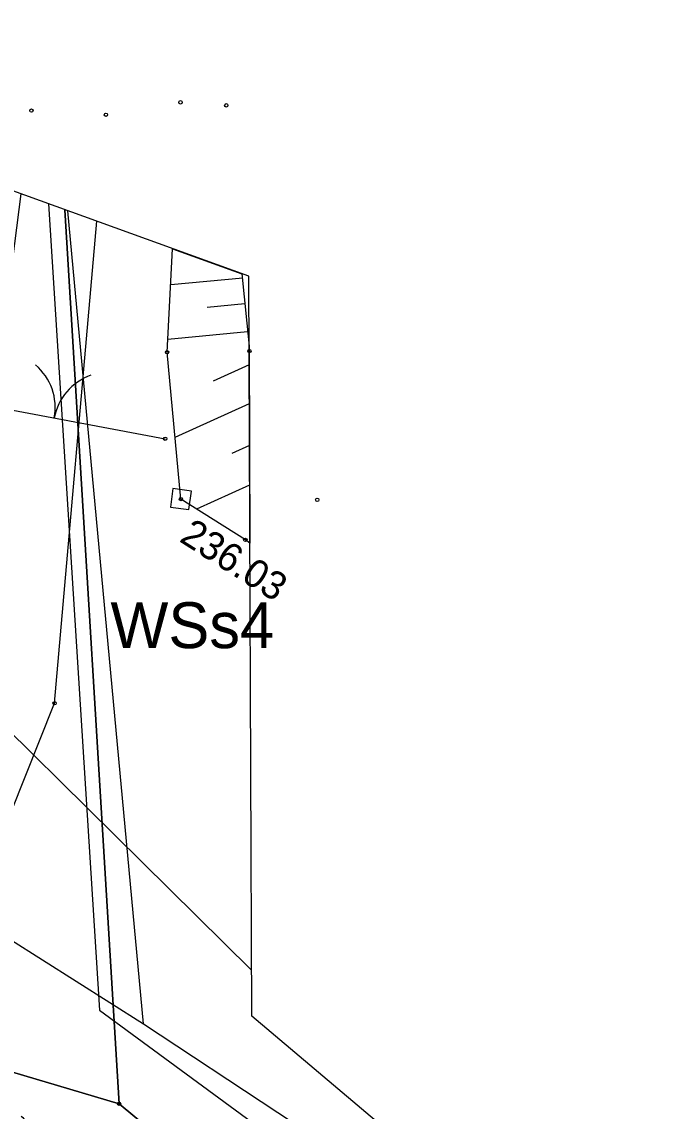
# Model space of a CAD drawing. Extents: x 6596400 to 6597200, y 5539751 to 5540251.
# Drawn here: x 6596816.16 to 6596833.15, y 5540075.21 to 5540104.29 of the extents above; entities that cross this region are included whole.
import ezdxf

# ---------------------------------------------------------------- set-up
doc = ezdxf.new("R2010")
doc.units = 0
for name, color, linetype in [('000 Inne (niezydentyfikowane)', 7, 'Continuous'), ('140-Punkty robocze', 7, 'Continuous'), ('203-punkt graniczny', 7, 'Continuous'), ('217-kontur klasyfikacyjny', 7, 'Continuous'), ('218-kontur użytku gruntowego', 7, 'Continuous'), ('219-działka ewidencyjna', 7, 'Continuous'), ('brama', 7, 'Continuous'), ('drzewo liściaste', 7, 'Continuous'), ('jezdnia', 7, 'Continuous'), ('Linia obszaru zagospodarowania terenu', 7, 'Continuous'), ('obudowa ochronna przewodu', 7, 'Continuous'), ('Opis obszaru zagospodarowania terenu', 7, 'Continuous'), ('pikieta sztuczna', 7, 'Continuous'), ('pikieta sztuczna-Atr2', 7, 'Continuous'), ('przewód telekomunikacyjny podziemny', 7, 'Continuous'), ('skarpa nieumocniona', 7, 'Continuous'), ('Strefa korytarza ekologicznego', 7, 'Continuous'), ('właz do komory lub kanału - kwadratowy', 7, 'Continuous'), ('Zakres', 7, 'Continuous')]:
    doc.layers.add(name, color=color, linetype=linetype)

# ---------------------------------------------------------------- blocks, each defined once
blk = doc.blocks.new('203')
blk.add_circle((0, 0), 0.045)
blk = doc.blocks.new('OP021')
blk.add_circle((0, 0), 0.05)
for centre, start, end in [((0, 0.4), 49.272, 130.728), ((-0.38, 0.124), 121.308, 202.548), ((0.38, 0.124), 337.452, 58.692), ((-0.235, -0.324), 193.221, 274.871), ((0.235, -0.324), 265.129, 346.779)]:
    blk.add_arc(centre, 0.4, start, end)
blk = doc.blocks.new('OK02')
for centre, start, end in [((-1.5, 0), 0, 60), ((1.5, 0), 120, 180)]:
    blk.add_arc(centre, 1.5, start, end)
blk = doc.blocks.new('US22A')
blk.add_lwpolyline([(-0.25, -0.25), (0.25, -0.25), (0.25, 0.25), (-0.25, 0.25)], close=True)
blk = doc.blocks.new('PIKIETA')
blk.add_circle((0, 0), 0.045)
blk = doc.blocks.new('PW01')
blk.add_circle((0, 0), 0.045)

msp = doc.modelspace()

# ---------------------------------------------------------------- linework, layer by layer
at = {"layer": '000 Inne (niezydentyfikowane)'}
for p, q in [((6596822.06, 5540097.45), (6596820.14, 5540097.27)), ((6596822.12, 5540096.76), (6596821.11, 5540096.66)), ((6596822.19, 5540096.01), (6596820.06, 5540095.81)), ((6596822.23, 5540095.132), (6596821.27, 5540094.7)), ((6596822.234, 5540094.095), (6596820.25, 5540093.19)), ((6596822.238, 5540092.981), (6596821.77, 5540092.77)), ((6596822.243, 5540091.925), (6596820.83, 5540091.28))]:
    msp.add_line(p, q, dxfattribs=at)
at = {"layer": '217-kontur klasyfikacyjny'}
for points in [[(6596818.76, 5540075.41), (6596817.316, 5540099.275)], [(6596803.31, 5540080), (6596818.76, 5540075.41)]]:
    msp.add_lwpolyline(points, dxfattribs=at)
at = {"layer": '218-kontur użytku gruntowego'}
for points in [[(6596817.316, 5540099.275), (6596818.76, 5540075.41)], [(6596818.76, 5540075.41), (6596817.316, 5540099.275)], [(6596818.76, 5540075.41), (6596803.31, 5540080)], [(6596803.31, 5540080), (6596818.76, 5540075.41)], [(6596818.76, 5540075.41), (6596830.806, 5540065.405)], [(6596830.806, 5540065.405), (6596818.76, 5540075.41)]]:
    msp.add_lwpolyline(points, dxfattribs=at)
at = {"layer": '219-działka ewidencyjna'}
for points in [[(6596818.76, 5540075.41), (6596817.316, 5540099.275)], [(6596818.76, 5540075.41), (6596803.31, 5540080)], [(6596830.806, 5540065.405), (6596818.76, 5540075.41)]]:
    msp.add_lwpolyline(points, dxfattribs=at)
at = {"layer": 'brama'}
msp.add_lwpolyline([(6596814.07, 5540094.27), (6596819.99, 5540093.16)], dxfattribs=at)
at = {"layer": 'jezdnia'}
msp.add_lwpolyline([(6596816.136, 5540099.702), (6596814.5, 5540086.93), (6596812.47, 5540082.2), (6596810.01, 5540078.61), (6596805.94, 5540076.86), (6596810.44, 5540074.77), (6596813.26, 5540073.35), (6596813.26, 5540075.57), (6596813.95, 5540078.37), (6596817.04, 5540086.1), (6596818.162, 5540098.968)], dxfattribs=at)
at = {"layer": 'Linia obszaru zagospodarowania terenu'}
for points in [[(6596664.616, 5540132.112), (6596671.21, 5540127.95), (6596681.8, 5540121.54), (6596690.35, 5540115.69), (6596701.61, 5540105.97), (6596709.34, 5540098.61), (6596715.39, 5540091.82), (6596718.63, 5540088.53), (6596721.87, 5540084.71), (6596726.1, 5540083.21), (6596730.7, 5540082.79), (6596730.91, 5540075), (6596745.51, 5540074.64), (6596746.77, 5540082.74), (6596765.15, 5540085.09), (6596776.62, 5540086.27), (6596789.34, 5540086.1), (6596798.37, 5540085.54), (6596805.65, 5540083.56), (6596813.11, 5540081.53), (6596819.41, 5540077.54), (6596826.58, 5540072.81), (6596832.721, 5540067.998)], [(6596819.41, 5540077.54), (6596817.394, 5540099.247)]]:
    msp.add_lwpolyline(points, dxfattribs=at)
at = {"layer": 'obudowa ochronna przewodu'}
msp.add_lwpolyline([(6596793.213, 5540107.981), (6596811.35, 5540089.78), (6596822.295, 5540078.976)], dxfattribs=at)
at = {"layer": 'przewód telekomunikacyjny podziemny'}
msp.add_lwpolyline([(6596822.295, 5540078.976), (6596811.35, 5540089.78), (6596793.213, 5540107.981)], dxfattribs=at)
at = {"layer": 'skarpa nieumocniona'}
msp.add_lwpolyline([(6596822.04, 5540097.56), (6596822.23, 5540095.63), (6596822.25, 5540090.37), (6596822.13, 5540090.46), (6596820.41, 5540091.55), (6596820.04, 5540095.47), (6596820.19, 5540098.23)], close=True, dxfattribs=at)
msp.add_lwpolyline([(6596822.04, 5540097.56), (6596822.23, 5540095.63), (6596822.25, 5540090.37), (6596822.13, 5540090.46), (6596820.41, 5540091.55), (6596820.04, 5540095.47), (6596820.19, 5540098.23)], close=True, dxfattribs=at)
at = {"layer": 'Strefa korytarza ekologicznego'}
msp.add_lwpolyline([(6596816.874, 5540099.435), (6596818.24, 5540077.91), (6596832.32, 5540067.56), (6596832.359, 5540067.509)], dxfattribs=at)
at = {"layer": 'Zakres'}
msp.add_lwpolyline([(6596822.22, 5540097.5), (6596800.39, 5540105.4), (6596755.76, 5540121.45), (6596697.73, 5540120.74), (6596659.35, 5540133.92), (6596647.64, 5540109.28), (6596697.73, 5540077), (6596721.01, 5540057.77), (6596727.72, 5540045.95), (6596731.95, 5540033.61), (6596741.17, 5540031.18), (6596755.59, 5540029.2), (6596757.85, 5540044.22), (6596787.25, 5540055.04), (6596806.3, 5540048.33), (6596813.97, 5540042.6), (6596833.15, 5540068.58), (6596822.3, 5540077.75)], close=True, dxfattribs=at)

# ---------------------------------------------------------------- block references
at = {"layer": '140-Punkty robocze'}
for p in [(6596820.4, 5540102.14), (6596821.62, 5540102.06), (6596816.42, 5540101.92), (6596818.41, 5540101.81), (6596820.04, 5540095.47), (6596822.24, 5540095.5), (6596819.99, 5540093.16), (6596820.41, 5540091.55), (6596824.05, 5540091.53), (6596817.04, 5540086.1)]:
    msp.add_blockref('PIKIETA', p, dxfattribs=at)
at = {"layer": '203-punkt graniczny'}
msp.add_blockref('203', (6596818.76, 5540075.41), dxfattribs=at)
at = {"layer": 'brama', "rotation": -10.620000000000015}
msp.add_blockref('OK02', (6596817.03, 5540093.715), dxfattribs=at)
at = {"layer": 'drzewo liściaste'}
msp.add_blockref('OP021', (6596815.56, 5540074.6), dxfattribs=at)
at = {"layer": 'pikieta sztuczna'}
msp.add_blockref('PW01', (6596822.13, 5540090.46), dxfattribs=at)
at = {"layer": 'właz do komory lub kanału - kwadratowy', "rotation": -97.78700000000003}
msp.add_blockref('US22A', (6596820.41, 5540091.55), dxfattribs=at)

# ---------------------------------------------------------------- texts
at = {"layer": 'Opis obszaru zagospodarowania terenu'}
msp.add_text('WSs4', height=1.225, dxfattribs=at).set_placement((6596818.53, 5540087.57))
at = {"layer": 'pikieta sztuczna-Atr2'}
msp.add_text('236.03', height=0.75, rotation=327.637, dxfattribs=at).set_placement((6596820.339, 5540090.436))

doc.saveas('drawing.dxf')
